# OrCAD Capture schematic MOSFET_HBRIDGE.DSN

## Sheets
1 PAGE2
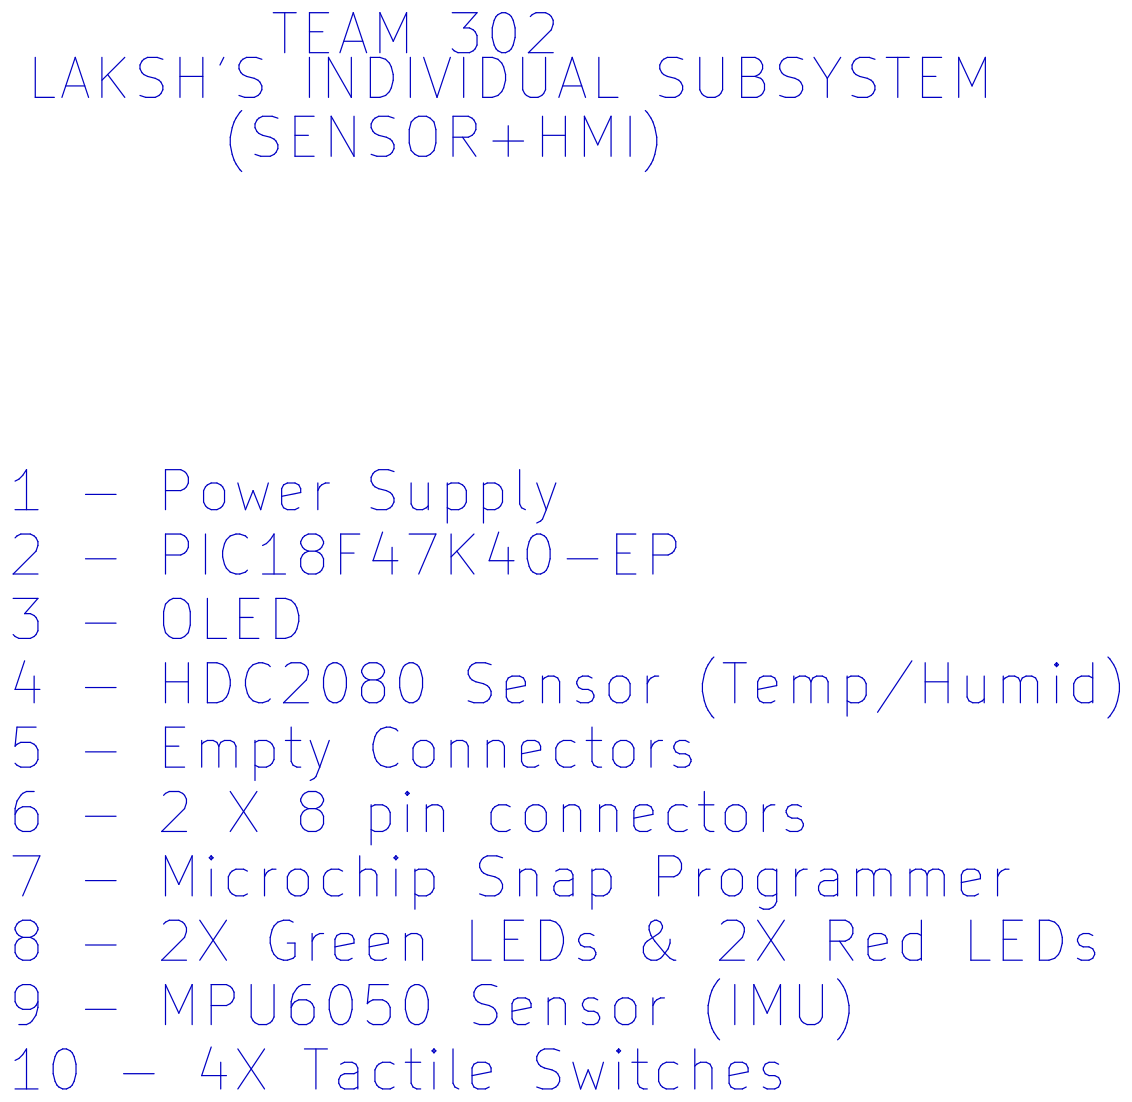
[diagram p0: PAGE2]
2 PAGE1: size A
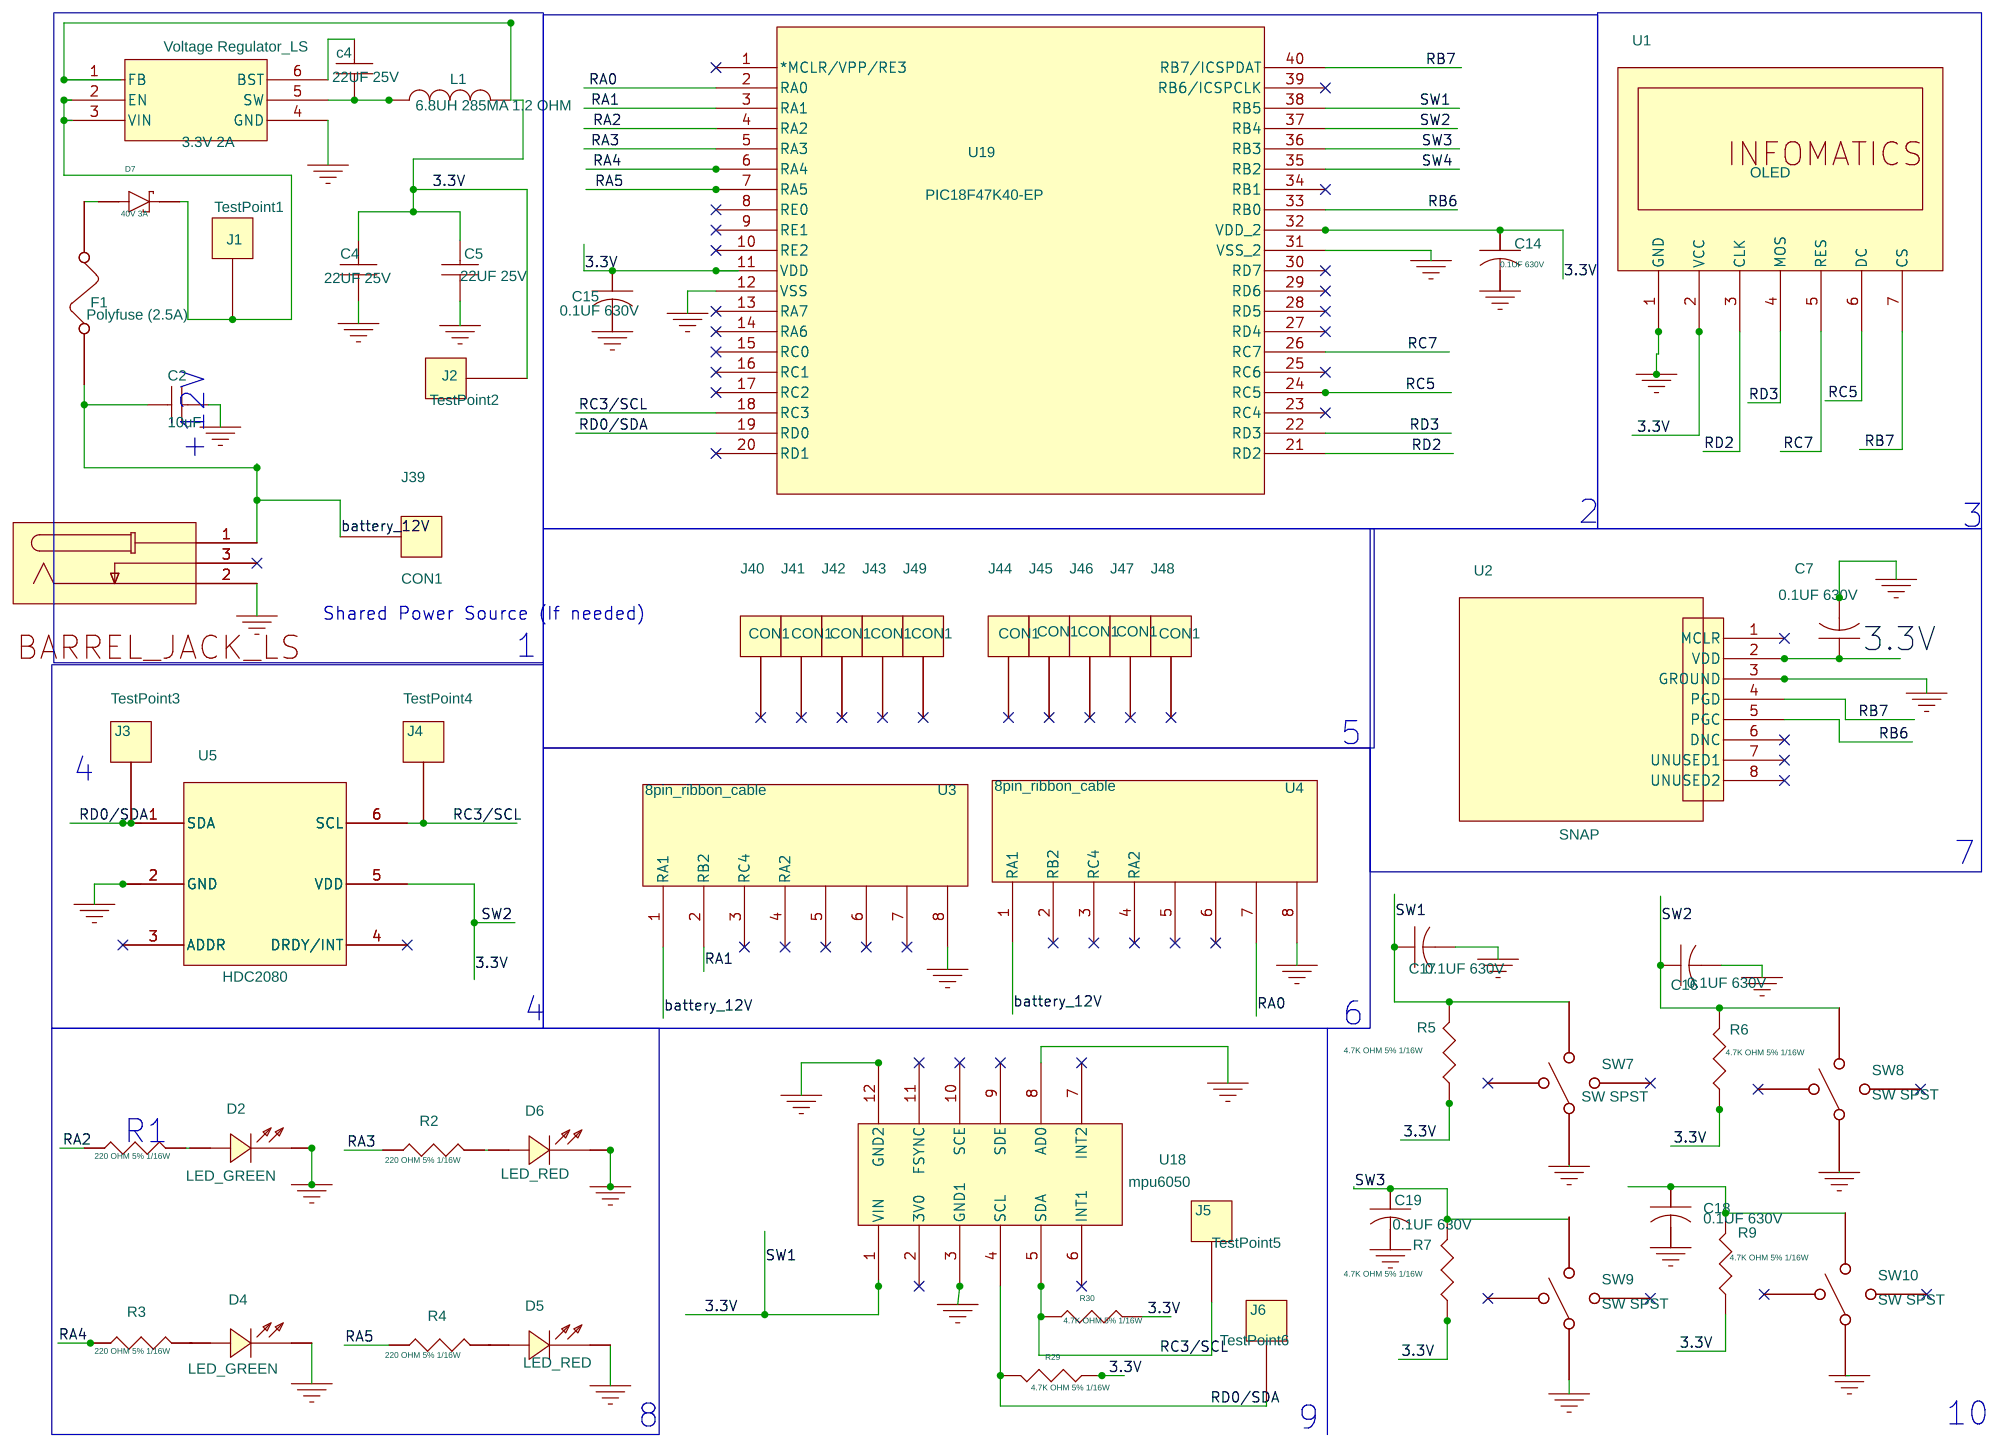
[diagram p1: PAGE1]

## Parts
C2  10uF  [C4532_Commercial]
c4  22UF 25V  [C4532_Commercial]
C5  22UF 25V  [C4532_Commercial]
C7  0.1UF 630V  [C4532_Commercial]
C14  0.1UF 630V  [C4532_Commercial]
C15  0.1UF 630V  [C4532_Commercial]
C16  0.1UF 630V
C17  0.1UF 630V
C18  0.1UF 630V
C19  0.1UF 630V
D2  LED_GREEN  [LED_LTST-C170GKT]
D4  LED_GREEN  [LED_LTST-C170GKT]
D5  LED_RED  [LED_SML-D12U1WT86]
D6  LED_RED  [LED_SML-D12U1WT86]
D7  40V 3A  [DIOM7959X261N]
F1  Polyfuse (2.5A)  [FUSE_01550900M_LTF]
J1  TestPoint1  [testpointconnectors]
J2  TestPoint2  [testpointconnectors]
J3  TestPoint3  [testpointconnectors]
J4  TestPoint4  [testpointconnectors]
J5  TestPoint5  [testpointconnectors]
J6  TestPoint6  [testpointconnectors]
J38  B_JACK  [NEB21R_LMB]
J39  CON1  [testpointconnectors]
J40  CON1  [testpointconnectors]
J41  CON1  [testpointconnectors]
J42  CON1  [testpointconnectors]
J43  CON1  [testpointconnectors]
J44  CON1  [testpointconnectors]
J45  CON1  [testpointconnectors]
J46  CON1  [testpointconnectors]
J47  CON1  [testpointconnectors]
J48  CON1  [testpointconnectors]
J49  CON1  [testpointconnectors]
L1  6.8UH 285MA 1.2 OHM  [IND_PM1812]
R2  220 OHM 5% 1/16W  [RESC1005X40N]
R3  220 OHM 5% 1/16W  [RESC1005X40N]
R4  220 OHM 5% 1/16W  [RESC1005X40N]
R5  4.7K OHM 5% 1/16W  [RESC1005X40N]
R6  4.7K OHM 5% 1/16W  [RESC1005X40N]
R7  4.7K OHM 5% 1/16W  [RESC1005X40N]
R9  4.7K OHM 5% 1/16W  [RESC1005X40N]
R29  4.7K OHM 5% 1/16W  [RESC1005X40N]
R30  4.7K OHM 5% 1/16W  [RESC1005X40N]
RF0  220 OHM 5% 1/16W  [RESC1005X40N]
SW7  SW SPST  [SON4_PTS526SM15SMTR2LFS_CNK]
SW8  SW SPST  [SON4_PTS526SM15SMTR2LFS_CNK]
SW9  SW SPST  [SON4_PTS526SM15SMTR2LFS_CNK]
SW10  SW SPST  [SON4_PTS526SM15SMTR2LFS_CNK]
U1  OLED  [SH1106]
U2  SNAP  [8pincon]
U3  8pin_ribbon_cable  [8pincon]
U4  8pin_ribbon_cable  [8pincon]
U5  HDC2080  [DMB0006A]
U18  mpu6050  [mpu60509dof]
U19  PIC18F47K40-EP  [PDIP40_600MIL_P_MCH]
Voltage Regulator_LS  3.3V 2A  [AP63203WU-7_DIO]

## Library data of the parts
C2 c4 C5 = CAP_NP
C7 = CAPACITOR
C14-C19 = CAP
D2 D4-D6 = LED
D7 = MBRS340T3G
F1 = FUSE_SM
J1-J6 J39-J49 = CON1
J38 = B_JACK_8
L1 = INDUCTOR
R2-R7 R9 R29 R30 RF0 = RESISTOR
SW7-SW10 = SW_SPST_1
U1 = OLED
U2 = Snap_1
U3 U4 = 8pin_ribbon_cable
U5 = TH_SENSOR
U18 = imu_1
U19 = PIC18F47K40-EP
Voltage Regulator_LS = VR_LS_13

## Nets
3.3V: C5.1 C7.1 C14.1 C15.1 C16.1 C17.1 J2.1 R5.1 R5.2 R6.1 R6.2 R7.1 R9.1 R29.1 R30.2 SW7.3 SW8.3 U1.2(VCC) U2.2(VDD) U5.5(VDD) U18.1(VIN) U19.11(VDD) U19.32(VDD_2) U19.37(RB4) U19.38(RB5)
GND: C2.2 C5.2 C7.2 C14.2 C15.2 C16.2 C17.2 C18.2 C19.2 D2.1(CATHODE) D4.1(CATHODE) D5.1(CATHODE) D6.1(CATHODE) J38.2 SW7.1 SW8.1 SW9.1 SW10.1 U1.1(GND) U2.3(GROUND) U3.8 U4.8 U18.3(GND1) U18.8(AD0) U18.12(GND2) U19.12(VSS) U19.31(VSS_2) Voltage Regulator_LS.4(GND)
0: U5.2(GND)
battery_12V: C2.1 F1.1 J38.1 J39.1 U3.1(RA1) U4.1(RA1)
RA0: U4.7 U19.2(RA0)
RA1: U3.2(RB2) U19.3(RA1)
RA2: RF0.1 U19.4(RA2)
RA3: R2.1 U19.5(RA3)
RA4: R3.1 U19.6(RA4)
RA5: R4.1 U19.7(RA5)
RB6: U2.5(PGC) U19.33(RB0)
RB7: U1.7(CS) U2.4(PGD) U19.40(RB7/ICSPDAT)
RC3/SCL: J4.1 J5.1 R30.1 U5.6(SCL) U18.5(SDA) U19.18(RC3)
RC5: U1.6(DC) U19.24(RC5)
RC7: U1.5(RES) U19.26(RC7)
RD0/SDA: J3.1 J6.1 R29.2 U5.1(SDA) U18.4(SCL) U19.19(RD0)
RD2: U1.3(CLK) U19.21(RD2)
RD3: U1.4(MOS) U19.22(RD3)
SW3: C19.1 R7.2 SW9.3 U19.36(RB3)
SW4: U19.35(RB2)
N134000: D7.C(K) J1.1 Voltage Regulator_LS.2(EN) Voltage Regulator_LS.3(VIN)
N134858: D2.2(ANODE) RF0.2
N146446: C18.1 R9.2 SW10.3
N147515: D6.2(ANODE) R2.2
N173046: L1.2 Voltage Regulator_LS.1(FB)
N173405: c4.1 Voltage Regulator_LS.6(BST)
N173558: c4.2 L1.1 Voltage Regulator_LS.5(SW)
N176386: D7.A F1.2
N207613: D5.2(ANODE) R4.2
N207615: D4.2(ANODE) R3.2

Not connected (* = marked no-connect by the designer): J38 3*; J40 1*; J41 1*; J42 1*; J43 1*; J44 1*; J45 1*; J46 1*; J47 1*; J48 1*; J49 1*; SW7 2* 4*; SW8 2* 4*; SW9 2* 4*; SW10 2* 4*; U2 1(MCLR)* 6(DNC)* 7(UNUSED1)* 8(UNUSED2)*; U3 3(RC4)* 4(RA2)* 5* 6* 7*; U4 2(RB2)* 3(RC4)* 4(RA2)* 5* 6*; U5 3(ADDR)* 4(DRDY/INT)*; U18 2(3V0)* 6(INT1)* 7(INT2)* 9(SDE)* 10(SCE)* 11(FSYNC)*; U19 1(*MCLR/VPP/RE3)* 8(RE0)* 9(RE1)* 10(RE2)* 13(RA7)* 14(RA6)* 15(RC0)* 16(RC1)* 17(RC2)* 20(RD1)* 23(RC4)* 25(RC6)* 27(RD4)* 28(RD5)* 29(RD6)* 30(RD7)* 34(RB1)* 39(RB6/ICSPCLK)*

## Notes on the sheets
sheet 1
- TEAM 302
- LAKSH'S INDIVIDUAL SUBSYSTEM
- (SENSOR+HMI)
- 1 - Power Supply
  2 - PIC18F47K40-EP
  3 - OLED
  4 - HDC2080 Sensor (Temp/Humid)
  5 - Empty Connectors
  6 - 2 X 8 pin connectors
  7 - Microchip Snap Programmer
  8 - 2X Green LEDs & 2X Red LEDs
  9 - MPU6050 Sensor (IMU)
  10 - 4X Tactile Switches
sheet 2
- +12V
- 2
- 3
- Shared Power Source (If needed)
- 1
- 5
- 4
- 7
- 4
- 6
- R1
- 8
- 9
- 10
